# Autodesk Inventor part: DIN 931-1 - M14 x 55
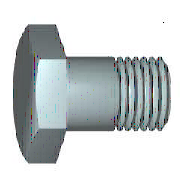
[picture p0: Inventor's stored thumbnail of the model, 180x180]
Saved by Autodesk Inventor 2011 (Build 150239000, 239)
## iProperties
Created: 2010-02
Part Number: DIN 931-1 - M14 x 55
Material: Steel, Mild
Description: Hex-Head Bolt
Document SubType Name: Modeling
Standard: DIN 931-1
Designer: PC
Standard Revision: 2001
Standards Organization: DIN
Language: en-US
Size Designation: M14 x 55
Categories: <MemberInstance><Categories><Category DisplayName="Fasteners" InternalName="e4da775c-781d-43d5-af7c-5136215cf5a6" Mnemonic="FSTN"><Category DisplayName="Bolts"
Density: 1 g/cm^3
IsCustomPart: 0
Author: PC
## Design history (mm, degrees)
workplane "Work Plane1"
revolve "Body" stored, may be unused: angle "d12" = 90 deg
sketch "Sketch2"
  geometry: L1 (0, 12.702)-(11, 6.351); L2 (11, 6.351)-(11, -6.351); L3 (11, -6.351)-(0, -12.702); L4 (0, -12.702)-(-11, -6.351); L5 (-11, -6.351)-(-11, 6.351); L6 (-11, 6.351)-(0, 12.702); 2 further points
  constraints: 12 end point, 1 coincident, 1 vertical, 11 other
  dimensions: "d11" = 22 distance between parallel lines of L5 L2 (= SW)
extrude "Head" join sketch "Sketch2" distance "d3" = 8.2 (= KOH - SD); taper "d4" = 0 deg
revolve "Chamfer1" stored, may be unused: angle "d21" = 90 deg
body "Solid1"
feature "Thread" dims "d15" = 34 (= GEL), "d16" = 0
chamfer "Chamfer2" distance "d6" = 1.2269 (= -0.5 x SPD + 0.5 x GD); stored, may be unused: second distance "d7" = 1.227 (computed from GUL), angle "d55" = 45 deg
sketch "Sketch1"
  geometry: L1 (0, 10.25)-(0, 7); L2 (21, 7)-(55, 7); L3 (55, 7)-(55, 0); L4 (55, 0)-(-0.6, 0); L5 (-11.72, 0)-(66.12, 0) reference; L6 (-0.6, 0)-(-0.6, 10.25); L7 (-0.6, 10.25)-(0, 10.25); L8 (21, 7)-(19.773, 7); L9 (19.773, 7)-(0, 7); L10 (0, -2.05)-(0, 12.3) reference
  constraints: 16 end point, 2 collinear, 2 perpendicular, 1 parallel
  dimensions: "d0" = 55 distance between parallel lines of L3 L1 (= NLG); "d1" = 34 distance from line of L2.start L3 (= GEL); "d2" = 14 diameter of L2 L4 (= GD); "d9" = 0.6001 distance between parallel lines of L6 L1 (computed from SD); "d10" = 20.5 diameter of L7 L4 (= SD2); "d13" = 1.227 distance of L2.start L8.end (computed from GAL); "d14" = 14 diameter of L9 L4 (= BDM)
sketch "Sketch4"
  geometry: L1 (-8.8, 11)-(-8.8, 12.702); L2 (-8.8, 12.702)-(-7.818, 12.702); L3 (-7.818, 12.702)-(-8.8, 11); L4 (-10.44, 0)-(1.04, 0) reference; L5 (-0.6, 12.702)-(-8.8, 12.702) reference; L6 (-8.8, 6.351)-(-8.8, 12.702) reference
  constraints: 6 end point, 2 collinear, 1 perpendicular, 1 vertical
  dimensions: "d5" = 30 deg angle of L3 L1 (= ANG1); "d19" = 22 diameter of L1.start L4 (= SW0)
other parameters: "NLG" = 55 [user parameter; used in 1 equation term], "GD" = 14 (= NND) [user parameter; used in 2 equation terms], "BDM" = 14 (= NND) [user parameter; used in 1 equation term], "KOH" = 8.8 [user parameter; used in 1 equation term], "GEL" = 34 [user parameter; used in 2 equation terms], "SW" = 22 [user parameter; used in 3 equation terms], "SW0" = 22 (= SW) [user parameter; used in 1 equation term], "SPD" = 11.5462 (= NND - 1.2269 x PTC) [user parameter; used in 1 equation term], "SD2" = 20.5 [user parameter; used in 1 equation term], "SD" = 0.6 [user parameter; used in 2 equation terms], "ANG1" = 30 deg [user parameter; used in 1 equation term], "GAL" = 1.2269 (= 0.61345 x PTC) [user parameter; used in 1 equation term], "GUL" = 1.2269 (= 0.61345 x PTC) [user parameter; used in 1 equation term], "d8" = 0, "RR" = 0.6 [user parameter], "d57" = 0, "d58" = 0, "TPU" = 5 (computed from PTC) [user parameter], "GD1" = 11.5462 (= THREADDIA - 1.2269 x PTC) [user parameter], "THREADDIA" = 14 [user parameter; used in 1 equation term], "TOA" = 30 deg [user parameter], "PTC" = 2 [user parameter; used in 5 equation terms], "NND" = 14 [user parameter; used in 3 equation terms], "E0" = 25.41 (= 1.155 x SW) [user parameter]
